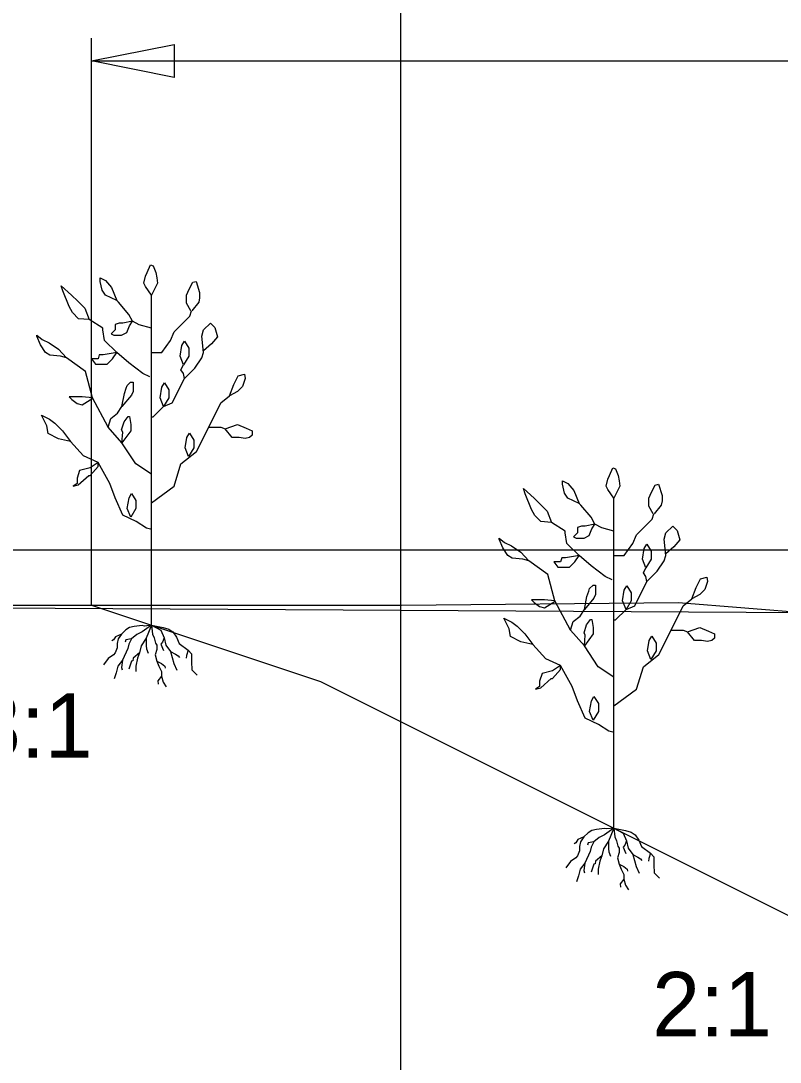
# Model space of a CAD drawing. Extents: x 1578769 to 1579225, y 724002 to 724828.
# Drawn here: x 1578843.47 to 1578848.99, y 724453.75 to 724461.32 of the extents above; entities that cross this region are included whole.
import ezdxf

# ---------------------------------------------------------------- set-up
doc = ezdxf.new("R2010")
doc.units = 0
for name, color, linetype in [('1', 7, 'Continuous'), ('Default', 7, 'Continuous'), ('Old_Level_41', 7, 'Continuous'), ('R_Exist Surface', 7, 'Continuous'), ('R_Fin Surface', 7, 'Continuous')]:
    doc.layers.add(name, color=color, linetype=linetype)

msp = doc.modelspace()

# ---------------------------------------------------------------- linework, layer by layer
at = {"layer": '1'}
for p, q in [((1578843.9799, 724457.0731), (1578843.9799, 724461.1985)), ((1578843.9799, 724461.0315), (1578851.7014, 724461.0315)), ((1578844.4159, 724456.9277), (1578844.4159, 724459.3277)), ((1578847.7782, 724455.4513), (1578847.7782, 724457.8513)), ((1578844.4206, 724456.9227), (1578844.4224, 724456.9267)), ((1578847.7829, 724455.4463), (1578847.7847, 724455.4504))]:
    msp.add_line(p, q, dxfattribs=at)
for points in [[(1578844.5799, 724460.9115), (1578843.9799, 724461.0315), (1578844.5799, 724461.1515)], [(1578844.4159, 724459.3277), (1578844.3718, 724459.3908), (1578844.3591, 724459.4161), (1578844.3718, 724459.4666), (1578844.3844, 724459.4919), (1578844.4096, 724459.5487), (1578844.4286, 724459.5424), (1578844.4475, 724459.4919), (1578844.4538, 724459.454), (1578844.4601, 724459.4161)], [(1578843.9615, 724459.1508), (1578843.8858, 724459.1572), (1578843.8416, 724459.2014), (1578843.8164, 724459.2456), (1578843.7722, 724459.3593), (1578843.7596, 724459.3972), (1578843.8353, 724459.3277), (1578843.8795, 724459.2835), (1578843.93, 724459.233)], [(1578844.1634, 724459.2898), (1578844.0814, 724459.3277), (1578844.0562, 724459.3656), (1578844.0436, 724459.4287), (1578844.0436, 724459.454), (1578844.0814, 724459.4351), (1578844.1256, 724459.3845)], [(1578844.277, 724459.1382), (1578844.2085, 724459.1236), (1578844.1798, 724459.1236), (1578844.1512, 724459.114), (1578844.1512, 724459.0758), (1578844.1226, 724459.0471), (1578844.1417, 724459.0376), (1578844.1989, 724459.0376), (1578844.2371, 724459.0567), (1578844.2562, 724459.1045)], [(1578844.1634, 724458.9108), (1578844.1226, 724458.9038), (1578844.0653, 724458.8943), (1578844.0366, 724458.8943), (1578844.0271, 724458.8656), (1578843.9794, 724458.8656), (1578844.008, 724458.8274), (1578844.0462, 724458.8274), (1578844.0939, 724458.8274), (1578844.1321, 724458.8656)], [(1578844.2013, 724458.5193), (1578844.2203, 724458.614), (1578844.2329, 724458.6519), (1578844.2392, 724458.6709), (1578844.2644, 724458.6961), (1578844.2834, 724458.6961), (1578844.2834, 724458.6266), (1578844.2708, 724458.6014)], [(1578843.8266, 724458.2638), (1578843.7407, 724458.2829), (1578843.6643, 724458.3211), (1578843.6548, 724458.3784), (1578843.6166, 724458.4548), (1578843.6739, 724458.4262), (1578843.7121, 724458.3975), (1578843.7693, 724458.3402), (1578843.798, 724458.302)], [(1578844.2013, 724458.254), (1578844.2085, 724458.3306), (1578844.1989, 724458.3497), (1578844.218, 724458.4071), (1578844.2467, 724458.4453), (1578844.2562, 724458.4453), (1578844.2658, 724458.3879), (1578844.2658, 724458.3402)], [(1578844.0271, 724458.1109), (1578843.9698, 724458.0727), (1578843.8934, 724458.0536), (1578843.8744, 724457.9963), (1578843.8744, 724457.958), (1578843.8457, 724457.9389), (1578843.8839, 724457.9485), (1578843.9603, 724458.0154), (1578843.9698, 724458.0154), (1578844.0271, 724458.0822)], [(1578847.7782, 724457.8513), (1578847.7341, 724457.9145), (1578847.7214, 724457.9397), (1578847.7341, 724457.9903), (1578847.7467, 724458.0155), (1578847.7719, 724458.0724), (1578847.7909, 724458.066), (1578847.8098, 724458.0155), (1578847.8161, 724457.9776), (1578847.8224, 724457.9397)], [(1578847.5258, 724457.8134), (1578847.4438, 724457.8513), (1578847.4185, 724457.8892), (1578847.4059, 724457.9524), (1578847.4059, 724457.9776), (1578847.4438, 724457.9587), (1578847.4879, 724457.9082)], [(1578847.3238, 724457.6744), (1578847.2481, 724457.6808), (1578847.2039, 724457.725), (1578847.1787, 724457.7692), (1578847.1345, 724457.8829), (1578847.1219, 724457.9208), (1578847.1976, 724457.8513), (1578847.2418, 724457.8071), (1578847.2923, 724457.7566)], [(1578847.6394, 724457.6618), (1578847.5708, 724457.6472), (1578847.5422, 724457.6472), (1578847.5135, 724457.6376), (1578847.5135, 724457.5994), (1578847.4849, 724457.5707), (1578847.504, 724457.5612), (1578847.5612, 724457.5612), (1578847.5994, 724457.5803), (1578847.6185, 724457.6281)], [(1578847.5258, 724457.4345), (1578847.4849, 724457.4274), (1578847.4276, 724457.4179), (1578847.399, 724457.4179), (1578847.3894, 724457.3892), (1578847.3417, 724457.3892), (1578847.3703, 724457.351), (1578847.4085, 724457.351), (1578847.4562, 724457.351), (1578847.4944, 724457.3892)], [(1578847.5636, 724457.0429), (1578847.5826, 724457.1376), (1578847.5952, 724457.1755), (1578847.6015, 724457.1945), (1578847.6267, 724457.2197), (1578847.6457, 724457.2197), (1578847.6457, 724457.1502), (1578847.6331, 724457.125)], [(1578847.1889, 724456.7874), (1578847.103, 724456.8065), (1578847.0266, 724456.8447), (1578847.0171, 724456.902), (1578846.9789, 724456.9784), (1578847.0362, 724456.9498), (1578847.0744, 724456.9211), (1578847.1317, 724456.8638), (1578847.1603, 724456.8256)], [(1578847.5636, 724456.7776), (1578847.5708, 724456.8542), (1578847.5612, 724456.8733), (1578847.5803, 724456.9307), (1578847.609, 724456.9689), (1578847.6185, 724456.9689), (1578847.6281, 724456.9116), (1578847.6281, 724456.8638)], [(1578847.3894, 724456.6345), (1578847.3321, 724456.5963), (1578847.2558, 724456.5772), (1578847.2367, 724456.5199), (1578847.2367, 724456.4817), (1578847.208, 724456.4625), (1578847.2462, 724456.4721), (1578847.3226, 724456.539), (1578847.3321, 724456.539), (1578847.3894, 724456.6058)]]:
    msp.add_lwpolyline(points, close=True, dxfattribs=at)
for points in [[(1578844.703, 724459.214), (1578844.6715, 724459.2708), (1578844.6715, 724459.3277), (1578844.6904, 724459.3719), (1578844.7157, 724459.4224), (1578844.7409, 724459.4287), (1578844.7662, 724459.3466), (1578844.7662, 724459.3087), (1578844.7599, 724459.2772), (1578844.7094, 724459.214)], [(1578844.4159, 724459.0877), (1578844.3275, 724459.1129), (1578844.277, 724459.1382), (1578844.2518, 724459.1887), (1578844.1761, 724459.2771), (1578844.1634, 724459.2898)], [(1578844.4159, 724458.9108), (1578844.4916, 724458.9108), (1578844.5547, 724458.9993), (1578844.58, 724459.0624), (1578844.6936, 724459.1761), (1578844.7062, 724459.214)], [(1578844.4033, 724458.734), (1578844.3528, 724458.7593), (1578844.2518, 724458.8351), (1578844.1634, 724458.9108), (1578844.0751, 724458.9993), (1578844.0625, 724459.075), (1578844.0625, 724459.0877), (1578843.9615, 724459.1508)], [(1578844.7946, 724458.9108), (1578844.782, 724459.0308), (1578844.7946, 724459.0751), (1578844.8451, 724459.1256), (1578844.8767, 724459.094), (1578844.8956, 724459.0245), (1578844.8514, 724458.974), (1578844.7946, 724458.9235)], [(1578843.7974, 724458.8729), (1578843.7533, 724458.8856), (1578843.6775, 724458.8919), (1578843.646, 724458.9109), (1578843.6081, 724458.9677), (1578843.5829, 724459.0308), (1578843.5829, 724459.0372), (1578843.6207, 724459.0056), (1578843.6712, 724458.9803), (1578843.7406, 724458.9361), (1578843.7974, 724458.8729)], [(1578844.6494, 724458.8224), (1578844.6242, 724458.8856), (1578844.6368, 724458.9614), (1578844.6557, 724458.993), (1578844.6873, 724458.9424), (1578844.6873, 724458.8856), (1578844.6494, 724458.8224)], [(1578844.4159, 724458.0267), (1578844.3023, 724458.1024), (1578844.2013, 724458.254), (1578844.1003, 724458.3677), (1578843.9867, 724458.5824), (1578843.9362, 724458.7719), (1578843.7974, 724458.8729)], [(1578844.4159, 724458.4435), (1578844.4285, 724458.4435), (1578844.5042, 724458.5193), (1578844.5674, 724458.5445), (1578844.6557, 724458.7214), (1578844.7314, 724458.7972), (1578844.7819, 724458.8729), (1578844.7946, 724458.9108)], [(1578844.6557, 724458.7214), (1578844.6494, 724458.7593), (1578844.6305, 724458.7845), (1578844.6494, 724458.8224)], [(1578844.9839, 724458.5951), (1578845.0155, 724458.6772), (1578845.047, 724458.7403), (1578845.0912, 724458.753), (1578845.0975, 724458.7214), (1578845.0786, 724458.6646), (1578845.0407, 724458.6267), (1578844.9839, 724458.5951)], [(1578844.5042, 724458.5193), (1578844.479, 724458.5824), (1578844.4916, 724458.6582), (1578844.5105, 724458.6898), (1578844.5421, 724458.6393), (1578844.5421, 724458.5824), (1578844.5042, 724458.5193)], [(1578843.9867, 724458.5824), (1578843.9125, 724458.5886), (1578843.8553, 724458.5886), (1578843.8171, 724458.5886), (1578843.8362, 724458.5695), (1578843.8743, 724458.5408), (1578843.9125, 724458.5312), (1578843.9889, 724458.579)], [(1578844.4159, 724457.8188), (1578844.58, 724457.9382), (1578844.6305, 724458.1024), (1578844.7441, 724458.1909), (1578844.8324, 724458.3677), (1578844.9208, 724458.5445), (1578844.9839, 724458.5951)], [(1578844.1003, 724458.3677), (1578844.1193, 724458.4309), (1578844.1698, 724458.4688), (1578844.2013, 724458.5193)], [(1578844.8324, 724458.3677), (1578844.8956, 724458.3677), (1578844.9208, 724458.3677), (1578844.9524, 724458.3551)], [(1578844.9524, 724458.3551), (1578845.0407, 724458.3866), (1578845.1038, 724458.3614), (1578845.148, 724458.3424), (1578845.148, 724458.3109), (1578845.1291, 724458.2919), (1578845.0975, 724458.2856), (1578845.0533, 724458.2919), (1578845.0029, 724458.2919), (1578844.9524, 724458.3551)], [(1578844.4185, 724457.6237), (1578844.3803, 724457.6332), (1578844.304, 724457.681), (1578844.2085, 724457.7288), (1578844.1512, 724457.853), (1578844.113, 724457.958), (1578844.0271, 724458.1109), (1578843.9221, 724458.1587), (1578843.8266, 724458.2638), (1578843.8266, 724458.2638)], [(1578844.6852, 724458.1537), (1578844.66, 724458.2168), (1578844.6726, 724458.2926), (1578844.6915, 724458.3242), (1578844.7231, 724458.2737), (1578844.7231, 724458.2168), (1578844.6852, 724458.1537)], [(1578848.0653, 724457.7376), (1578848.0338, 724457.7945), (1578848.0338, 724457.8513), (1578848.0527, 724457.8955), (1578848.078, 724457.946), (1578848.1032, 724457.9524), (1578848.1285, 724457.8702), (1578848.1285, 724457.8324), (1578848.1222, 724457.8008), (1578848.0717, 724457.7376)], [(1578844.2652, 724457.7142), (1578844.2399, 724457.7774), (1578844.2526, 724457.8532), (1578844.2715, 724457.8848), (1578844.3031, 724457.8342), (1578844.3031, 724457.7774), (1578844.2652, 724457.7142)], [(1578847.7782, 724457.6113), (1578847.6898, 724457.6366), (1578847.6394, 724457.6618), (1578847.6141, 724457.7123), (1578847.5384, 724457.8008), (1578847.5258, 724457.8134)], [(1578847.7782, 724457.4345), (1578847.8539, 724457.4345), (1578847.917, 724457.5229), (1578847.9423, 724457.586), (1578848.0559, 724457.6997), (1578848.0685, 724457.7376)], [(1578847.7656, 724457.2576), (1578847.7151, 724457.2829), (1578847.6141, 724457.3587), (1578847.5258, 724457.4345), (1578847.4374, 724457.5229), (1578847.4248, 724457.5987), (1578847.4248, 724457.6113), (1578847.3238, 724457.6744)], [(1578848.1569, 724457.4345), (1578848.1443, 724457.5545), (1578848.1569, 724457.5987), (1578848.2074, 724457.6492), (1578848.239, 724457.6176), (1578848.2579, 724457.5482), (1578848.2137, 724457.4976), (1578848.1569, 724457.4471)], [(1578847.1597, 724457.3966), (1578847.1156, 724457.4092), (1578847.0399, 724457.4155), (1578847.0083, 724457.4345), (1578846.9704, 724457.4913), (1578846.9452, 724457.5545), (1578846.9452, 724457.5608), (1578846.9831, 724457.5292), (1578847.0335, 724457.5039), (1578847.103, 724457.4597), (1578847.1597, 724457.3966)], [(1578848.0117, 724457.346), (1578847.9865, 724457.4092), (1578847.9991, 724457.485), (1578848.018, 724457.5166), (1578848.0496, 724457.466), (1578848.0496, 724457.4092), (1578848.0117, 724457.346)], [(1578847.7782, 724456.9671), (1578847.7908, 724456.9671), (1578847.8666, 724457.0429), (1578847.9297, 724457.0681), (1578848.018, 724457.245), (1578848.0938, 724457.3208), (1578848.1442, 724457.3966), (1578848.1569, 724457.4345)], [(1578847.7782, 724456.5503), (1578847.6646, 724456.6261), (1578847.5636, 724456.7776), (1578847.4626, 724456.8913), (1578847.349, 724457.106), (1578847.2986, 724457.2955), (1578847.1597, 724457.3966)], [(1578848.018, 724457.245), (1578848.0117, 724457.2829), (1578847.9928, 724457.3081), (1578848.0117, 724457.346)], [(1578848.3462, 724457.1187), (1578848.3778, 724457.2008), (1578848.4094, 724457.2639), (1578848.4535, 724457.2766), (1578848.4599, 724457.245), (1578848.4409, 724457.1882), (1578848.4031, 724457.1503), (1578848.3462, 724457.1187)], [(1578847.8666, 724457.0429), (1578847.8413, 724457.106), (1578847.8539, 724457.1818), (1578847.8729, 724457.2134), (1578847.9044, 724457.1629), (1578847.9044, 724457.106), (1578847.8666, 724457.0429)], [(1578847.7782, 724456.3424), (1578847.9423, 724456.4618), (1578847.9928, 724456.6261), (1578848.1064, 724456.7145), (1578848.1947, 724456.8913), (1578848.2831, 724457.0681), (1578848.3462, 724457.1187)], [(1578847.349, 724457.106), (1578847.2748, 724457.1122), (1578847.2176, 724457.1122), (1578847.1794, 724457.1122), (1578847.1985, 724457.0931), (1578847.2367, 724457.0644), (1578847.2748, 724457.0549), (1578847.3512, 724457.1026)], [(1578847.4626, 724456.8913), (1578847.4816, 724456.9545), (1578847.5321, 724456.9924), (1578847.5636, 724457.0429)], [(1578844.4159, 724456.9277), (1578844.3645, 724456.9219), (1578844.349, 724456.9258), (1578844.2908, 724456.918), (1578844.2558, 724456.9103), (1578844.2287, 724456.8947), (1578844.1977, 724456.8637), (1578844.1744, 724456.8287), (1578844.1666, 724456.7938), (1578844.1666, 724456.7627), (1578844.1511, 724456.7278), (1578844.1394, 724456.7123), (1578844.1007, 724456.6851), (1578844.0658, 724456.6385)], [(1578844.4159, 724456.9277), (1578844.349, 724456.8792), (1578844.3102, 724456.8598), (1578844.2714, 724456.8287), (1578844.252, 724456.7899), (1578844.2442, 724456.7588), (1578844.2054, 724456.6735), (1578844.1705, 724456.6307), (1578844.1589, 724456.5803), (1578844.1433, 724456.5375)], [(1578844.4159, 724456.9277), (1578844.3761, 724456.8326), (1578844.3412, 724456.7783), (1578844.3296, 724456.7278), (1578844.314, 724456.689), (1578844.3024, 724456.6307), (1578844.3024, 724456.5919)], [(1578844.4159, 724456.9277), (1578844.4998, 724456.9116), (1578844.5429, 724456.8986), (1578844.5701, 724456.8792), (1578844.5972, 724456.8404), (1578844.6166, 724456.7938), (1578844.6826, 724456.7472), (1578844.7059, 724456.72), (1578844.7059, 724456.6618), (1578844.7098, 724456.6036), (1578844.7486, 724456.5647)], [(1578844.4159, 724456.9277), (1578844.4847, 724456.8908), (1578844.508, 724456.8365), (1578844.5197, 724456.7821), (1578844.5546, 724456.7356), (1578844.5779, 724456.6501), (1578844.6011, 724456.5997)], [(1578844.4159, 724456.9277), (1578844.4227, 724456.8637), (1578844.4343, 724456.8365), (1578844.446, 724456.7977), (1578844.4537, 724456.7821), (1578844.4537, 724456.7511), (1578844.4421, 724456.7123), (1578844.4537, 724456.6657), (1578844.4692, 724456.6307), (1578844.4886, 724456.5919), (1578844.4886, 724456.557), (1578844.5003, 724456.5143), (1578844.5235, 724456.4793)], [(1578848.1947, 724456.8913), (1578848.2579, 724456.8913), (1578848.2831, 724456.8913), (1578848.3147, 724456.8787)], [(1578848.3147, 724456.8787), (1578848.403, 724456.9102), (1578848.4661, 724456.885), (1578848.5103, 724456.866), (1578848.5103, 724456.8345), (1578848.4914, 724456.8155), (1578848.4598, 724456.8092), (1578848.4156, 724456.8155), (1578848.3652, 724456.8155), (1578848.3147, 724456.8787)], [(1578844.1977, 724456.8637), (1578844.155, 724456.8443), (1578844.1394, 724456.821), (1578844.1278, 724456.8132)], [(1578844.2714, 724456.8287), (1578844.2287, 724456.821), (1578844.2248, 724456.8054)], [(1578844.3761, 724456.8326), (1578844.3761, 724456.7783), (1578844.38, 724456.755), (1578844.3916, 724456.7239)], [(1578844.508, 724456.8365), (1578844.4964, 724456.8054), (1578844.4847, 724456.7899), (1578844.5041, 724456.7433)], [(1578848.0475, 724456.6773), (1578848.0223, 724456.7404), (1578848.0349, 724456.8162), (1578848.0538, 724456.8478), (1578848.0854, 724456.7973), (1578848.0854, 724456.7404), (1578848.0475, 724456.6773)], [(1578844.6826, 724456.7472), (1578844.671, 724456.7084), (1578844.6671, 724456.689)], [(1578847.7808, 724456.1473), (1578847.7426, 724456.1568), (1578847.6663, 724456.2046), (1578847.5708, 724456.2524), (1578847.5135, 724456.3766), (1578847.4753, 724456.4817), (1578847.3894, 724456.6345), (1578847.2844, 724456.6823), (1578847.1889, 724456.7874), (1578847.1889, 724456.7874)], [(1578844.2054, 724456.6735), (1578844.1977, 724456.6191), (1578844.2015, 724456.6036)], [(1578844.3296, 724456.7278), (1578844.283, 724456.689), (1578844.2791, 724456.6696), (1578844.2714, 724456.6657), (1578844.252, 724456.6074)], [(1578844.4537, 724456.6657), (1578844.4886, 724456.6501), (1578844.5119, 724456.6307), (1578844.5158, 724456.6152)], [(1578844.5546, 724456.7356), (1578844.5895, 724456.7161), (1578844.6089, 724456.7045), (1578844.6205, 724456.6929)], [(1578844.4886, 724456.557), (1578844.4615, 724456.522), (1578844.4654, 724456.4987)], [(1578847.6275, 724456.2378), (1578847.6022, 724456.301), (1578847.6149, 724456.3768), (1578847.6338, 724456.4084), (1578847.6654, 724456.3578), (1578847.6654, 724456.301), (1578847.6275, 724456.2378)], [(1578847.7782, 724455.4513), (1578847.7268, 724455.4455), (1578847.7113, 724455.4494), (1578847.6531, 724455.4417), (1578847.6182, 724455.4339), (1578847.591, 724455.4183), (1578847.56, 724455.3873), (1578847.5367, 724455.3523), (1578847.5289, 724455.3174), (1578847.5289, 724455.2863), (1578847.5134, 724455.2514), (1578847.5018, 724455.2359), (1578847.463, 724455.2087), (1578847.4281, 724455.1621)], [(1578847.7782, 724455.4513), (1578847.7113, 724455.4028), (1578847.6725, 724455.3834), (1578847.6337, 724455.3523), (1578847.6143, 724455.3135), (1578847.6065, 724455.2825), (1578847.5677, 724455.1971), (1578847.5328, 724455.1543), (1578847.5212, 724455.1039), (1578847.5056, 724455.0612)], [(1578847.7782, 724455.4513), (1578847.7384, 724455.3562), (1578847.7035, 724455.3019), (1578847.6919, 724455.2514), (1578847.6763, 724455.2126), (1578847.6647, 724455.1543), (1578847.6647, 724455.1155)], [(1578847.7782, 724455.4513), (1578847.8622, 724455.4352), (1578847.9052, 724455.4222), (1578847.9324, 724455.4028), (1578847.9595, 724455.364), (1578847.979, 724455.3174), (1578848.0449, 724455.2708), (1578848.0682, 724455.2437), (1578848.0682, 724455.1854), (1578848.0721, 724455.1272), (1578848.1109, 724455.0884)], [(1578847.7782, 724455.4513), (1578847.847, 724455.4145), (1578847.8704, 724455.3601), (1578847.882, 724455.3057), (1578847.9169, 724455.2592), (1578847.9402, 724455.1737), (1578847.9634, 724455.1233)], [(1578847.7782, 724455.4513), (1578847.785, 724455.3873), (1578847.7966, 724455.3601), (1578847.8083, 724455.3213), (1578847.816, 724455.3057), (1578847.816, 724455.2747), (1578847.8044, 724455.2359), (1578847.816, 724455.1893), (1578847.8315, 724455.1543), (1578847.8509, 724455.1155), (1578847.8509, 724455.0806), (1578847.8626, 724455.0379), (1578847.8858, 724455.0029)], [(1578847.56, 724455.3873), (1578847.5173, 724455.3679), (1578847.5018, 724455.3446), (1578847.4901, 724455.3368)], [(1578847.6337, 724455.3523), (1578847.591, 724455.3446), (1578847.5871, 724455.329)], [(1578847.7384, 724455.3562), (1578847.7384, 724455.3019), (1578847.7423, 724455.2786), (1578847.754, 724455.2475)], [(1578847.8704, 724455.3601), (1578847.8587, 724455.329), (1578847.847, 724455.3135), (1578847.8665, 724455.2669)], [(1578847.6919, 724455.2514), (1578847.6453, 724455.2126), (1578847.6415, 724455.1932), (1578847.6337, 724455.1893), (1578847.6143, 724455.1311)], [(1578847.9169, 724455.2592), (1578847.9518, 724455.2398), (1578847.9712, 724455.2281), (1578847.9828, 724455.2165)], [(1578848.0449, 724455.2708), (1578848.0333, 724455.232), (1578848.0294, 724455.2126)], [(1578847.5677, 724455.1971), (1578847.56, 724455.1427), (1578847.5638, 724455.1272)], [(1578847.816, 724455.1893), (1578847.8509, 724455.1737), (1578847.8742, 724455.1543), (1578847.8781, 724455.1388)], [(1578847.8509, 724455.0806), (1578847.8238, 724455.0456), (1578847.8277, 724455.0224)]]:
    msp.add_lwpolyline(points, dxfattribs=at)
at = {"layer": 'Default'}
msp.add_lwpolyline([(1578841.2303, 724457.0713), (1578842.2603, 724457.0594), (1578863.3303, 724456.9426), (1578874.2903, 724456.8851), (1578876.4003, 724454.7965), (1578883.1703, 724446.7822), (1578901.0203, 724441.7105), (1578903.4503, 724441.0286), (1578909.9203, 724441.3768), (1578926.3203, 724442.247), (1578964.0903, 724446.5535), (1578966.7003, 724446.865), (1578977.3903, 724447.8421), (1578995.6903, 724449.505), (1578999.6003, 724449.8412), (1579038.5003, 724453.3659)], dxfattribs=at)
at = {"layer": 'Old_Level_41'}
msp.add_line((1578846.2303, 724437.4737), (1578846.2303, 724467.4737), dxfattribs=at)
msp.add_lwpolyline([(1578921.2303, 724457.4737), (1578821.2303, 724457.4737)], dxfattribs=at)
at = {"layer": 'R_Exist Surface'}
msp.add_lwpolyline([(1578821.2303, 724457.0959), (1578841.2026, 724457.0731), (1578846.2342, 724457.0731), (1578848.2493, 724457.0932), (1578849.212, 724457.0151), (1578855.2225, 724457.0281), (1578858.2375, 724457.0216), (1578859.2523, 724457.0346), (1578860.202, 724456.9175), (1578863.1422, 724456.9565), (1578870.1545, 724456.9565), (1578871.1481, 724456.8987), (1578871.4213, 724456.8727), (1578874.2445, 724456.8987), (1578875.1161, 724456.0135), (1578876.1829, 724454.946), (1578880.2119, 724450.2709), (1578880.8595, 724449.5135), (1578883.2557, 724446.7468), (1578884.9705, 724446.2805), (1578895.0791, 724443.3873), (1578896.2567, 724443.0569)], dxfattribs=at)
at = {"layer": 'R_Fin Surface'}
for p, q in [((1578843.9799, 724457.0731), (1578845.6445, 724456.5182)), ((1578843.9799, 724457.0731), (1578845.6445, 724456.5182)), ((1578845.6445, 724456.5182), (1578851.7014, 724453.4898)), ((1578845.6445, 724456.5182), (1578851.7014, 724453.4898))]:
    msp.add_line(p, q, dxfattribs=at)

# ---------------------------------------------------------------- texts
at = {"layer": '1'}
for s, p in [('3:1', (1578843.1167, 724455.9639)), ('2:1', (1578848.057, 724453.9367))]:
    msp.add_text(s, height=0.46875, dxfattribs=at).set_placement(p)

doc.saveas('drawing.dxf')
